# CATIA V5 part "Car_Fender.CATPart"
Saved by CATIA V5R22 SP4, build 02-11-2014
Part number: Car_Fender
Material "ｱﾙﾐﾆｳﾑ": density 2710 kg/m3, Young's modulus 7e+10 Pa, Poisson ratio 0.346, thermal expansion 2.36e-05 1/K
Bounding box of the stored display mesh (mm): x -800 to 0, y -40 to 122.298, z 0 to 580
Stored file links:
  C:\DATA\Car_ASSY\教育モデル\5_ASM\Car_Fender.CATPart
  C:\DATA\Car_ASSY\Car_Fender.CATPart
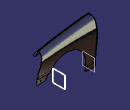
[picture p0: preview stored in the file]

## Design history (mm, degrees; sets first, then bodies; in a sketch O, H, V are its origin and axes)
Set1
  Plane1: type Offset, RefPlane yz-plane, Offset 400, reversed
  Plane2: type Offset, RefPlane Plane1, Offset 400, reversed
  Plane3: type Offset, RefPlane yz-plane, Offset 390, reversed
Body1 (main body)
  Body2
    Sketch1 on yz-plane, origin (0, 0, 0), H (0, 1, 0), V (0, 0, 1)
      point P4 (100, 50)
      point P5 (10, 450)
      spline S1 through (10, 450) (100, 50)
      line L1 (0, 450) -> (10, 450)
      line L2 (0, 0) -> (0, 450)
      line L3 (100, 0) -> (0, 0)
      line L4 (100, 50) -> (100, 0)
      point P6 (100, 50)
      point P7 (10, 450)
      distance P4 L3 = 50
      distance P5 L2 = 10
      distance L4 L2 = 100
      distance L1 H = 450
      coincidence: L2 V, H L3, P4 P6, P7 P5
    Sketch2 on Plane1, origin (-400, 0, 0), H (0, 1, 0), V (0, 0, 1)
      point P4 (100, 50)
      point P5 (10, 530)
      spline S1 through (10, 530) (100, 50)
      line L1 (0, 530) -> (10, 530)
      line L2 (0, 0) -> (0, 530)
      line L3 (100, 0) -> (0, 0)
      line L4 (100, 50) -> (100, 0)
      point P6 (100, 50)
      point P7 (10, 530)
      distance P4 L3 = 50
      distance P5 L2 = 10
      distance L4 L2 = 100
      distance L1 H = 530
      coincidence: L2 V, H L3, P4 P6, P7 P5
    Sketch3 on Plane2, origin (-800, 0, 0), H (0, 1, 0), V (0, 0, 1)
      point P4 (100, 50)
      point P5 (10, 580)
      spline S1 through (10, 580) (100, 50)
      line L1 (0, 580) -> (10, 580)
      line L2 (0, 0) -> (0, 580)
      line L3 (100, 0) -> (0, 0)
      line L4 (100, 50) -> (100, 0)
      point P6 (100, 50)
      point P7 (10, 580)
      distance P4 L3 = 50
      distance P5 L2 = 10
      distance L4 L2 = 100
      distance L1 H = 580
      coincidence: L2 V, H L3, P4 P6, P7 P5
    Loft1: solid, Sections (Sketch1; Sketch2; Sketch3)
    Body3
      Sketch4 on zx-plane, origin (0, 0, 0), H (-1, 0, 0), V (0, 0, 1)
        line L1 (-46.4952, 240) -> (159.0779, 240)
        arc A1 centre (390, 110) radius 265 from (159.0779, 240) to (655, 109.9999) cw
        point P2 (390, 110)
        line L2 (655, 109.9999) -> (655, -30)
        line L3 (-46.4952, 626.6258) -> (850, 626.6258)
        line L4 (850, 626.6258) -> (850, -30)
        line L5 (850, -30) -> (655, -30)
        line L6 (-46.4952, 626.6258) -> (-46.4952, 240)
        radius A1 = 265
        distance P2 H = 110
        distance V P2 = 390
        distance H L1 = 240
        horizontal: L1 H, L3 H, L5 H
        tangency: L2 A1
        vertical: L2 V, L4 V, L6 V
      Pad1: profile Sketch4, direction (0, 1, 0), length 340, mirrored extent
    Intersect1: tool Body3
    Shell1: ExtOffset 0, Face (face of Loft1; face of Pad1 from Sketch4.A1; face of Pad1 from Sketch4.L1; face of Loft1; face of Loft1; face of Loft1), IntOffset 3
    Sketch5 on Plane2, origin (-800, 0, 0), H (0, 1, 0), V (0, 0, 1)
      line L1 (0, 580) -> (0, 545)
      line L2 (-5, 540) -> (-40, 540)
      point P2 (-40, 540)
      reference projected line E1 (10, 580) -> (0, 580)
      reference intersected line E2 (0, 0) -> (0, 580)
      arc A1 centre (-5, 545) radius 5 from (-5, 540) to (0, 545) ccw
      line L3 (-5, 537) -> (-40, 537)
      arc A2 centre (-5, 545) radius 8 from (-5, 537) to (3, 545) ccw
      line L4 (3, 580) -> (3, 545)
      line L5 (-40, 537) -> (-40, 540)
      line L6 (3, 580) -> (0, 580)
      reference projected line E3 (10, 580) -> (0, 580)
      distance E1 L2 = 40
      radius A1 = 5
      distance L1 P2 = 40
      length L5 = 3
      length L6 = 3
      radius A2 = 8
      vertical: L1 V, L4 V, L5 V
      horizontal: L2 H, L6 H, L3 H
      coincidence: L1 E2, L6 E3
      tangency: A1 L2, A1 L1, L4 A2, A2 L3
    Rib1: profile Sketch5, centre curve edge [face of Loft1 | face of Loft1]
    Sketch6 on Plane2, origin (-800, 0, 0), H (0, 1, 0), V (0, 0, 1)
      projected curve E1 from edge [face of Shell1 | face of Rib1]
      projected line E2 (10, 576.9862) -> (3, 576.9862) from edge [face of Shell1 | face of Rib1]
      point P4 (3, 576.9862)
      projected line E3 (3, 576.9862) -> (3, 545) from edge [face of Rib1 | face of Rib1]
      projected line E4 (3, 576.9862) -> (3, 399.233) from edge [face of Rib1 | face of Rib1]
      point P5 (3, 576.9862)
      projected line E5 (97, 0) -> (97, 50) from edge [face of Shell1 | face of Rib1]
      line L1 (97, 0) -> (37, 0)
      line L2 (37, 0) -> (17.9077, 155.4943)
      arc A1 centre (2003, 399.233) radius 2000 from (3, 399.233) to (17.9077, 155.4943) ccw
      angle L1 L2 = 97
      length L1 = 60
      radius A1 = 2000
      horizontal: L1 H
      tangency: A1 E3, A1 L2
      coincidence: P4 P5
    Pad2: profile Sketch6, direction (1, 0, 0), length 10, opposite side length -7
    Sketch7 on yz-plane, origin (0, 0, 0), H (0, 1, 0), V (0, 0, 1)
      projected curve E1 from edge [face of Loft1 | face of Shell1]
      projected curve E2 from edge [face of Loft1 | face of Shell1]
      point P1 (103.8705, 240)
      line L1 (100.927, 243) -> (92.1161, 243)
      line L2 (86.1161, 237) -> (86.1161, 160)
      line L3 (86.1161, 160) -> (89.1161, 160)
      line L4 (89.1161, 160) -> (89.1161, 237)
      point P5 (103.8705, 240)
      line L5 (101.1067, 267.4285) -> (104.1068, 267.4285)
      point P6 (101.1068, 267.4285)
      point P7 (104.1068, 267.4285)
      offset curve E3 from edge [face of Loft1 | face of Shell1]
      offset curve E4 from edge [face of Loft1 | face of Shell1]
      line L6 (92.1161, 240) -> (103.8705, 240)
      arc A1 centre (92.1161, 237) radius 3 from (92.1161, 240) to (89.1161, 237) ccw
      arc A2 centre (92.1161, 237) radius 6 from (92.1161, 243) to (86.1161, 237) ccw
      distance L4 L2 = 3
      distance P6 P7 = 3
      distance L4 E1 = 15
      distance L1 L6 = 3
      radius A1 = 3
      radius A2 = 6
      distance L6 L3 = 80
      horizontal: L1 H, L3 H, L5 H, L6 H
      vertical: L2 V, L4 V
      coincidence: P7 E1, E3 P6, P6 L5, P7 L5, P5 P1
      tangency: A1 L6, A1 L4, A2 L1, A2 L2
    Rib2: profile Sketch7, centre curve edge [face of Pad1 from Sketch4.L1 | face of Shell1]
    Body4
      Sketch8 on zx-plane, origin (0, 0, 0), H (-1, 0, 0), V (0, 0, 1)
        point P1 (0, 300)
        line L1 (0, 300) -> (127.0171, 520)
        line L2 (127.0171, 520) -> (-100, 520)
        line L3 (-100, 520) -> (-100, 300)
        line L4 (-100, 300) -> (0, 300)
        angle L1 L4 = 120
        distance L4 H = 300
        coincidence: P1 V
        horizontal: L2 H, L4 H
        vertical: L3 V
      Pad3: profile Sketch8, direction (0, 1, 0), length 220, mirrored extent
    Remove1: tool Body4
    Sketch9 on xy-plane, origin (0, 0, 0), H (1, 0, 0), V (0, 1, 0)
      line L1 (-730, -50.1266) -> (-730, -25)
      arc A1 centre (-725, -25) radius 5 from (-730, -25) to (-720, -25) cw
      point P3 (-725, -25)
      line L2 (-720, -25) -> (-720, -50.1266)
      line L3 (-720, -50.1266) -> (-730, -50.1266)
      reference projected line E1 (-5.7993, -40) -> (-800, -40) from edge [face of Rib1 | face of Rib1]
      reference projected line E2 (-800, -40) -> (-800, -5) from edge [face of Rib1 | face of Rib1]
      radius A1 = 5
      distance P3 E1 = 15
      distance P3 E2 = 75
      vertical: L1 V, L2 V
      tangency: A1 L1, L2 A1
      horizontal: L3 H
    Pocket1: profile Sketch9, direction (0, 0, 1), length 660
    RectPattern1: of Pocket1, direction 1 instances 3, spacing 270, along X axis
    Sketch10 on {plane type Tangent, Support face of Rib2, RefPoint {point type OnSurface, Support face of Rib2, RefPoint {point stored without definition}, Length 0, Direction (0, 0, -1000)}}, origin (-99.3533, 90.7181, 174.1703), H (0.9999, -0.0138, 0), V (0, 0, 1)
      point P1 (49.366, 15.8297)
      reference projected line E1 (99.366, -14.1703) -> (99.366, 62.8297) from edge [face of Rib2 | face of Rib2]
      reference projected line E2 (-59.6229, -14.1703) -> (99.366, -14.1703) from edge [face of Rib2 | face of Rib2]
      distance P1 E1 = 50
      distance P1 E2 = 30
    Hole1: placed by Sketch10, at (-49.9929, 89.9835, 190) direction (-0.016, -0.9999, 0), diameter 15, depth 15
    Chamfer1: length 70, angle 35, on edge [face of Rib2 | face of Rib2]
    Fillet1: radius 10, on edge [face of Rib1 | face of Rib1]; edge [face of Rib1 | face of Pad3 from Sketch8.L1]
    Fillet2: radius 5, on edge [face of Rib2 | face of Chamfer1]; edge [face of Chamfer1 | face of Rib2]; edge [face of Rib2 | face of Rib2]
    Fillet3: radius 10, on edge [face of Pad1 from Sketch4.L2 | face of Pad2]
  Add1: tool Body2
